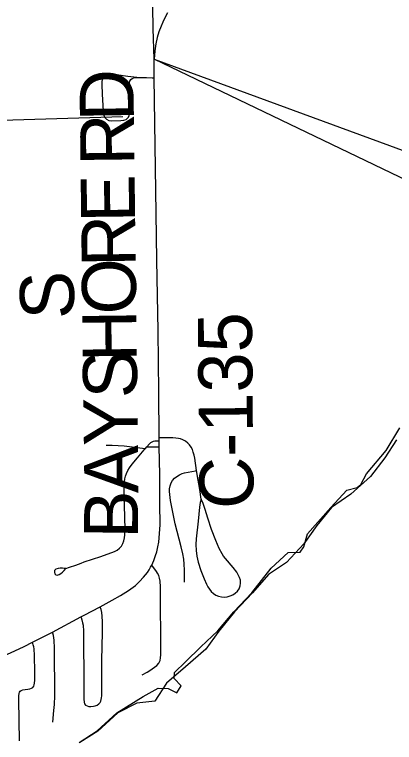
# Model space of a CAD drawing. Extents: x -12 to 34, y 0 to 22.
# Drawn here: x 5.999 to 6.399, y 15.79 to 16.556 of the extents above; entities that cross this region are included whole.
import ezdxf

# ---------------------------------------------------------------- set-up
doc = ezdxf.new("R2010")
doc.units = 0
for name, color, linetype in [('GM_X_Adjacent_County', 7, 'Continuous'), ('GM_X_Airport_Location_Class_2', 7, 'Continuous'), ('GM_X_Airport_Location_Class_3', 7, 'Continuous'), ('GM_X_County_Road', 7, 'Continuous'), ('GM_X_Major_Lake', 7, 'Continuous'), ('GM_X_Major_River', 7, 'Continuous'), ('GM_X_Minor_Lake', 7, 'Continuous'), ('GM_X_Minor_River', 7, 'Continuous'), ('GM_X_Township', 7, 'Continuous')]:
    doc.layers.add(name, color=color, linetype=linetype)

msp = doc.modelspace()

# ---------------------------------------------------------------- linework, layer by layer
at = {"layer": 'GM_X_Adjacent_County'}
msp.add_lwpolyline([(9.40596, 14.94351), (6.14543, 16.50898), (9.40596, 15.31296)], close=True, dxfattribs=at)
msp.add_lwpolyline([(9.40596, 14.94351), (6.14543, 16.50898), (9.40596, 15.31296)], dxfattribs=at)
at = {"layer": 'GM_X_Airport_Location_Class_2'}
msp.add_lwpolyline([(6.06654, 15.78991), (6.08551, 15.80206), (6.10638, 15.82106), (6.13407, 15.83827), (6.14989, 15.84714), (6.16019, 15.8469), (6.1693, 15.8421), (6.17385, 15.84953), (6.16666, 15.85721), (6.16691, 15.86343), (6.17865, 15.87494), (6.19471, 15.89076), (6.21264, 15.90729), (6.22933, 15.92742), (6.24831, 15.94756), (6.26877, 15.97345), (6.28675, 15.99), (6.29921, 15.99023), (6.30328, 15.99599), (6.30688, 16.00941), (6.33141, 16.03721), (6.34835, 16.05543), (6.35937, 16.0583), (6.363, 16.06151), (6.3692, 16.07269), (6.38982, 16.09737), (6.40419, 16.1211)], dxfattribs=at)
msp.add_lwpolyline([(6.06654, 15.78991), (6.08551, 15.80206), (6.10638, 15.82106), (6.13407, 15.83827), (6.14989, 15.84714), (6.16019, 15.8469), (6.1693, 15.8421), (6.17385, 15.84953), (6.16666, 15.85721), (6.16691, 15.86343), (6.17865, 15.87494), (6.19471, 15.89076), (6.21264, 15.90729), (6.22933, 15.92742), (6.24831, 15.94756), (6.26877, 15.97345), (6.28675, 15.99), (6.29921, 15.99023), (6.30328, 15.99599), (6.30688, 16.00941), (6.33141, 16.03721), (6.34835, 16.05543), (6.35937, 16.0583), (6.363, 16.06151), (6.3692, 16.07269), (6.38982, 16.09737), (6.40419, 16.1211)], dxfattribs=at)
at = {"layer": 'GM_X_Airport_Location_Class_3'}
msp.add_line((6.03841, 15.90618), (6.06838, 15.92213), dxfattribs=at)
for points in [[(6.14543, 16.48957), (6.14542, 16.49845), (6.14543, 16.50898)], [(6.15086, 16.11061), (6.15047, 16.15879), (6.14963, 16.22327), (6.14835, 16.29753), (6.14761, 16.3471), (6.14543, 16.48957)], [(6.15096, 16.10119), (6.15088, 16.106), (6.15089, 16.10752), (6.15086, 16.11061)], [(6.14301, 15.97658), (6.14512, 15.98144), (6.14705, 15.98659), (6.14829, 15.99063), (6.14953, 15.99573), (6.1504, 16.00082), (6.15127, 16.0098), (6.15175, 16.01913), (6.15163, 16.04093), (6.1515, 16.0719), (6.15096, 16.10119)], [(6.06838, 15.92213), (6.07187, 15.92399), (6.0888, 15.9328), (6.10139, 15.93969), (6.1102, 15.94454), (6.11843, 15.94983), (6.12577, 15.95526), (6.13015, 15.95943), (6.13452, 15.96397), (6.13842, 15.96893), (6.14016, 15.97158), (6.14173, 15.97432), (6.14301, 15.97658)], [(6.01755, 15.89533), (6.02807, 15.90068), (6.03841, 15.90618)], [(5.93258, 15.86193), (5.93731, 15.86318), (5.94508, 15.86542), (5.95698, 15.86932), (5.97153, 15.87478), (5.99448, 15.88433), (6.00865, 15.8908), (6.01755, 15.89533)]]:
    msp.add_lwpolyline(points, dxfattribs=at)
at = {"layer": 'GM_X_Major_Lake'}
msp.add_lwpolyline([(6.15955, 16.55778), (6.15713, 16.55335), (6.15464, 16.54801), (6.15289, 16.54365), (6.15062, 16.53772), (6.14885, 16.53179), (6.14739, 16.52533), (6.14618, 16.51786), (6.14543, 16.50898)], dxfattribs=at)
at = {"layer": 'GM_X_Major_River'}
msp.add_line((6.13633, 16.09942), (6.13773, 16.10091), dxfattribs=at)
for points in [[(6.14543, 16.50898), (6.14466, 16.54122), (6.14348, 16.61083)], [(6.12731, 16.48984), (6.11784, 16.49098), (6.10581, 16.49244), (6.10022, 16.4928), (6.09735, 16.49259), (6.09515, 16.492), (6.09328, 16.49084), (6.09137, 16.48864), (6.09044, 16.4857), (6.09038, 16.48253), (6.09082, 16.47241), (6.0919, 16.45421), (6.09228, 16.45107), (6.09331, 16.44821), (6.09524, 16.44603), (6.09789, 16.4447), (6.101, 16.44425), (6.11056, 16.44443), (6.1137, 16.44477), (6.11609, 16.44562), (6.11768, 16.44682), (6.11868, 16.44822), (6.11922, 16.44969), (6.11955, 16.45162), (6.11973, 16.45422), (6.11905, 16.47936), (6.11914, 16.48252), (6.11948, 16.48447), (6.12014, 16.48607), (6.12107, 16.48754), (6.12227, 16.4886), (6.12421, 16.48939), (6.12731, 16.48984)], [(6.12731, 16.48984), (6.1374, 16.4898), (6.14357, 16.48961), (6.14543, 16.48957)], [(6.19008, 16.07608), (6.18823, 16.08917), (6.18762, 16.09223), (6.18677, 16.09559), (6.1859, 16.09828), (6.18462, 16.10076), (6.18281, 16.10332), (6.18101, 16.10505), (6.17845, 16.10715), (6.17589, 16.1085), (6.17334, 16.10948), (6.17108, 16.10993), (6.16837, 16.11023), (6.16529, 16.11038), (6.15086, 16.11061)], [(6.13773, 16.10091), (6.14074, 16.10435), (6.1422, 16.1056), (6.14356, 16.10642), (6.14495, 16.10702), (6.14641, 16.10736), (6.14851, 16.10756), (6.15089, 16.10752)], [(6.05262, 15.97292), (6.0509, 15.97306), (6.04896, 15.97322), (6.04652, 15.97326), (6.04447, 15.97303), (6.04222, 15.9723), (6.04078, 15.97089), (6.04051, 15.9691), (6.04096, 15.96731), (6.04191, 15.9664), (6.04348, 15.96617), (6.04557, 15.96663), (6.04744, 15.96762), (6.04923, 15.96922), (6.05094, 15.97108), (6.05277, 15.97287), (6.05639, 15.97451), (6.06298, 15.9767), (6.06877, 15.9787), (6.07174, 15.97994), (6.08939, 15.98574), (6.10383, 15.99109), (6.10657, 15.9925), (6.10905, 15.99434), (6.11107, 15.99663), (6.11256, 15.9993), (6.11357, 16.00222), (6.11422, 16.00527), (6.1146, 16.00835), (6.11489, 16.01454), (6.11453, 16.03928), (6.11402, 16.05783), (6.11431, 16.06402), (6.11476, 16.06727), (6.11553, 16.07012), (6.11664, 16.07308), (6.11802, 16.07601), (6.11971, 16.07889), (6.12258, 16.08274), (6.12817, 16.08962), (6.13517, 16.09806), (6.13633, 16.09942)], [(6.095, 16.10274), (6.10128, 16.10288), (6.1076, 16.10263), (6.11386, 16.10205), (6.13325, 16.09976), (6.13633, 16.09942)], [(6.13773, 16.10091), (6.14169, 16.101), (6.15096, 16.10119)], [(6.17738, 15.95876), (6.17754, 15.97125), (6.17731, 15.97759), (6.17672, 15.98273), (6.17569, 15.9886), (6.17408, 15.9958), (6.16786, 16.02012), (6.16284, 16.04461), (6.16191, 16.0508), (6.16168, 16.05393), (6.1618, 16.05704), (6.16238, 16.06011), (6.16343, 16.06305), (6.16501, 16.06573), (6.16704, 16.06807), (6.16945, 16.07002), (6.17213, 16.0716), (6.17495, 16.07286), (6.17747, 16.07367), (6.18918, 16.0759), (6.19008, 16.07608)], [(6.19502, 16.04614), (6.19358, 16.05608), (6.19181, 16.0659), (6.19008, 16.07608)], [(6.19502, 16.04614), (6.19417, 16.04254), (6.19332, 16.03756), (6.19185, 16.02291), (6.18969, 16.0044), (6.18944, 15.99819), (6.18976, 15.99201), (6.19064, 15.98586), (6.192, 15.97981), (6.19474, 15.97092), (6.19811, 15.96224), (6.20065, 15.95657), (6.20207, 15.95381), (6.20372, 15.95119), (6.20571, 15.94881), (6.208, 15.94672), (6.21057, 15.94499), (6.21339, 15.94374), (6.2164, 15.94305), (6.21949, 15.94292), (6.22257, 15.94326), (6.22555, 15.9441), (6.22837, 15.94541), (6.23097, 15.94715), (6.23324, 15.94929), (6.23507, 15.9518), (6.23624, 15.95464), (6.23663, 15.95766), (6.23632, 15.9607), (6.23543, 15.96367), (6.2341, 15.96648), (6.23247, 15.9691), (6.2287, 15.97402), (6.22061, 15.98344), (6.21874, 15.98591), (6.21702, 15.98848), (6.21412, 15.99395), (6.21037, 16.00248), (6.20595, 16.01408), (6.20215, 16.02605), (6.19927, 16.03508), (6.19718, 16.04143), (6.19502, 16.04614)], [(6.13279, 15.86127), (6.13835, 15.86403), (6.14102, 15.86558), (6.14604, 15.86911), (6.14843, 15.87099), (6.1505, 15.87327), (6.15178, 15.87606), (6.15234, 15.87912), (6.15248, 15.88221), (6.15238, 15.95372), (6.1518, 15.95981), (6.15126, 15.96276), (6.15042, 15.96558), (6.14919, 15.96823), (6.14797, 15.97005), (6.14301, 15.97658)], [(6.06838, 15.92213), (6.06861, 15.92142), (6.06946, 15.91888), (6.07022, 15.91597), (6.07073, 15.91333), (6.07129, 15.90718), (6.0716, 15.84766), (6.0717, 15.83563), (6.07196, 15.83245), (6.07243, 15.83068), (6.07347, 15.82933), (6.07503, 15.82844), (6.07685, 15.82793), (6.07882, 15.82775), (6.08164, 15.82798), (6.08362, 15.82844), (6.08555, 15.82918), (6.08743, 15.83045), (6.08861, 15.83183), (6.08945, 15.83344), (6.08991, 15.83505), (6.09017, 15.83677), (6.09037, 15.83896), (6.09063, 15.85762), (6.09065, 15.87638), (6.09127, 15.90618), (6.09127, 15.91679), (6.09098, 15.92277), (6.09051, 15.92661), (6.0898, 15.93004), (6.08916, 15.93181), (6.0888, 15.9328)], [(6.03885, 15.81117), (6.03999, 15.82365), (6.04071, 15.8298), (6.04114, 15.83911), (6.04068, 15.88915), (6.04017, 15.89756), (6.03982, 15.89999), (6.03946, 15.90235), (6.03875, 15.90493), (6.03841, 15.90618)], [(6.00385, 15.79179), (6.00315, 15.83486), (6.00319, 15.83914), (6.00336, 15.84145), (6.00392, 15.8429), (6.00451, 15.84389), (6.00558, 15.84474), (6.00717, 15.84528), (6.00978, 15.8456), (6.0126, 15.84594), (6.01482, 15.84633), (6.01657, 15.84692), (6.0179, 15.84791), (6.01875, 15.84915), (6.01931, 15.85043), (6.01978, 15.85236), (6.02011, 15.85548), (6.02008, 15.86174), (6.01956, 15.8835), (6.01938, 15.88647), (6.01913, 15.88858), (6.01879, 15.89062), (6.01825, 15.89274), (6.01755, 15.89533)]]:
    msp.add_lwpolyline(points, dxfattribs=at)
at = {"layer": 'GM_X_Minor_Lake'}
msp.add_lwpolyline([(6.00784, 17.0347), (6.00459, 16.92713), (5.94884, 16.91318), (5.9497, 16.44378), (5.84644, 16.44064), (6.11255, 16.44872)], dxfattribs=at)
at = {"layer": 'GM_X_Minor_River'}
msp.add_lwpolyline([(6.40065, 16.10856), (6.38851, 16.08957), (6.37333, 16.06981), (6.35246, 16.0512), (6.33235, 16.03714), (6.31679, 16.01815), (6.30313, 15.99915), (6.28491, 15.9794), (6.26594, 15.96686), (6.24924, 15.94749), (6.23027, 15.92735), (6.21357, 15.90722), (6.19991, 15.88823), (6.17866, 15.86961), (6.15855, 15.85252), (6.14641, 15.83352), (6.12743, 15.83124), (6.10732, 15.82098), (6.08645, 15.80199), (6.06748, 15.78983)], dxfattribs=at)
at = {"layer": 'GM_X_Township'}
msp.add_lwpolyline([(6.15955, 16.55778), (6.15713, 16.55335), (6.15464, 16.54801), (6.15289, 16.54365), (6.15062, 16.53772), (6.14885, 16.53179), (6.14739, 16.52533), (6.14618, 16.51786), (6.14543, 16.50898)], dxfattribs=at)

# ---------------------------------------------------------------- texts
at = {"layer": 'GM_X_County_Road'}
for s, height, rotation, p in [('D', 0.05682, 90.69215, (6.12431, 16.44408)), ('R', 0.05682, 90.69309, (6.12487, 16.39742)), ('E', 0.05682, 90.69308, (6.1256, 16.33742)), ('R', 0.05682, 90.68725, (6.12616, 16.29075)), ('O', 0.05682, 90.69215, (6.12676, 16.24076)), ('S', 0.05682, 91.24465, (6.06174, 16.23594)), ('H', 0.05682, 90.69215, (6.12736, 16.19076)), ('C-135', 0.056818, 90.54577, (6.25031, 16.03597)), ('S', 0.05682, 90.69197, (6.12783, 16.15243)), ('Y', 0.05682, 90.69086, (6.12843, 16.10243)), ('A', 0.05682, 90.62606, (6.12898, 16.05236)), ('B', 0.05682, 89.24281, (6.12836, 16.0042))]:
    msp.add_text(s, height=height, rotation=rotation, dxfattribs=at).set_placement(p)

doc.saveas('drawing.dxf')
